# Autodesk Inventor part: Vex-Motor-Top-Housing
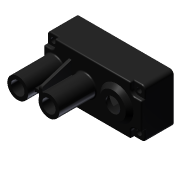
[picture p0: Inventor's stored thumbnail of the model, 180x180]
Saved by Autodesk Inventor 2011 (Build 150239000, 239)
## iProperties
Part Number: Vex-Motor-Top-Housing
Material: Alloy Steel
Document SubType Name: Modeling
Density: 7.85 g/cm^3
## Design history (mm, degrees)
feature "Base1"
body "Solid1"
